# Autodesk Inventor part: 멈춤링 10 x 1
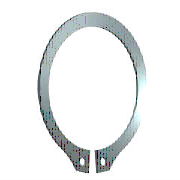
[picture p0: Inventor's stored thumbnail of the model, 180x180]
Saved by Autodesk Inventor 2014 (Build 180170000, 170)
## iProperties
IsCustomPart: 0
Company: 한국ATC센터
Created: 2009-02
Part Number: 멈춤링 10 x 1
Material: Steel, Mild
Description: 리테이닝 링(C형)
Document SubType Name: Modeling
Standard: KS B 1336
Designer: KYOUNG IL JANG
Standards Organization: KS
Language: ko-KR
Size Designation: 10 x 1
Categories: <MemberInstance><Categories><Category DisplayName="샤프트 부품" InternalName="7f7aeb1f-a693-4053-b835-cee3144e0d98" Mnemonic="SHFT"><Category DisplayName="써클립" Inter
Density: 7.86 g/cm^3
Mass: 0.423087 g
Surface Area: 1.9243 cm^2
Volume: 0.0538279 cm^3
Appearance: Metal-Steel
Author: KYOUNG IL JANG
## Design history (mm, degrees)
sketch "스케치1"
  geometry: L1 (-6, 0)-(6, 0) reference; L2 (0, 20.189)-(0, -80.536) reference; L3 (-48.09, 0)-(48.09, 0) reference; L4 (-0.3, -9.791)-(-0.3, -12.791); L5 (-0.3, -6.54)-(-0.3, -13.29); L6 (-2.795, 1.6)-(3.672, 1.6); L7 (0.3, -6.54)-(0.3, -13.29); L8 (0.3, -9.791)-(0.3, -12.791); C1 r 0.6 at (-1.2, -11.486); C2 r 0.6 at (1.2, -11.486); A1 r 4.8 centre (0, -5) between (0.3, -9.791) and (-0.3, -9.791); A2 r 6.2 centre (0, -4.6) between (2.988, -10.033) and (-2.988, -10.033); A3 r 7.796 centre (0, -5) between (-1.418, -12.666) and (-0.3, -12.791); A4 r 1.2 centre (-1.2, -11.486) between (-2.383, -11.285) and (-1.418, -12.666); A5 r 1.2 centre (-3.566, -11.084) between (-2.383, -11.285) and (-2.988, -10.033); A6 r 1.2 centre (3.566, -11.084) between (2.988, -10.033) and (2.383, -11.285); A7 r 1.2 centre (1.2, -11.486) between (1.418, -12.666) and (2.383, -11.285); A8 r 7.796 centre (0, -5) between (0.3, -12.791) and (1.418, -12.666)
  constraints: 16 point on circle, 12 end point, 10 centre point, 9 symmetric about line, 5 point on line, 4 tangent, 3 coincident, 2 horizontal, 1 perpendicular, 1 vertical, 5 other
  dimensions: "d0" = 9.6 diameter of A1 (= ND); "d1" = 3 distance of L4.end L4.start (= SRB2); "d6" = 0.3 distance between parallel lines of L2 L5 (= 0.25 x SD5); "d7" = 1.6 distance between parallel lines of L6 L3 (= SRB1); "d8" = 0.4 distance of A1.centre A2.centre (= 0.25 x SRB1); "d9" = 1.2 radius of A4 (= SD5); "d10" = 1.2 radius of A5 (= SD5); "d11" = 0.9 distance from line of L4 A4.centre (= 0.75 x SD5); "d12" = 1.2 diameter of C1 (= SD5); "d13" = 1.2 diameter of C2 (= SD5); "d14" = 5 distance from line of A1.centre L1 (= 0.5 x WD)
extrude "본체" new body sketch "스케치1" distance "d2" = 1 (= SD); taper "d3" = 0 deg
workaxis "Work Axis1"
workplane "Work Plane1"
body "Solid1"
other parameters: "SD" = 1 [user parameter; used in 1 equation term], "SRB1" = 1.6 [user parameter; used in 2 equation terms], "ND" = 9.6 [user parameter; used in 1 equation term], "SRB2" = 3 [user parameter; used in 1 equation term], "SD5" = 1.2 [user parameter; used in 6 equation terms], "d15" = 0, "d16" = 0, "d17" = 0, "d41" = 0, "d42" = 0, "SD3" = 9.3 [user parameter], "WDMAX" = 11 [user parameter]
